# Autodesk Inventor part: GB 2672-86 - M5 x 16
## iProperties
Library Location: C:\Program Files\Autodesk\Inventor 6\content
Library: local
SubLibrary: AFNOR
Family: 17
Member: 450
Member Major Revision: 1
Member Minor Revision: 1
Comments: To add or edit properties for Autodesk Inventor files, use iProperties.
Created: 2005-01
Part Number: GB 2672-86 - M5 x 16
Vendor: Autodesk Inc.
Document SubType Name: Modeling
Designer: Flavien MARTY
Description: Vis à tête hexagonale bombée à pans creux
Standard: GB 2672-86 M5 x 16
Alert: To add or edit properties for Autodesk Inventor files, use iProperties.
Control State: 0
Master: False
Checked Out: False
Shininess: 64.0
Length Units: 11269
Angle Units: 11279
Time Units: 11290
Mass Units: 11283
Length Display Precision: 3
Angle Display Precision: 2
Compacted: True
EGR: 1
Density: 0.0
Volumn: 0.0
Area: 0.0
PropertySet Name: Model Information
Author: Flavien MARTY
Revision Number: 1
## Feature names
1. Corps [Revolution]
2. Fente [Extrusion]
3. Congé1 [Fillet]
